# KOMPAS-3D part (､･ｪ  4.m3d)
File: created 29.01.2016 13:47:21, last saved 25.07.2016 11:42:22.
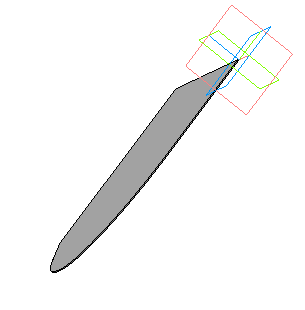
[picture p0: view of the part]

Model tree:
1. Эскиз:1
2. Операция выдавливания:1
     Толщина стенки 2 = 18; Расстояние 1 = 0.8
3. Эскиз:5
4. Вырезать элемент выдавливания:2
     Расстояние 1 = 10
5. Эскиз:6
6. Вырезать элемент выдавливания:3
     Расстояние 1 = 400
7. Эскиз:7
8. Вырезать элемент выдавливания:4
     Расстояние 2 = 400; Расстояние 1 = 400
